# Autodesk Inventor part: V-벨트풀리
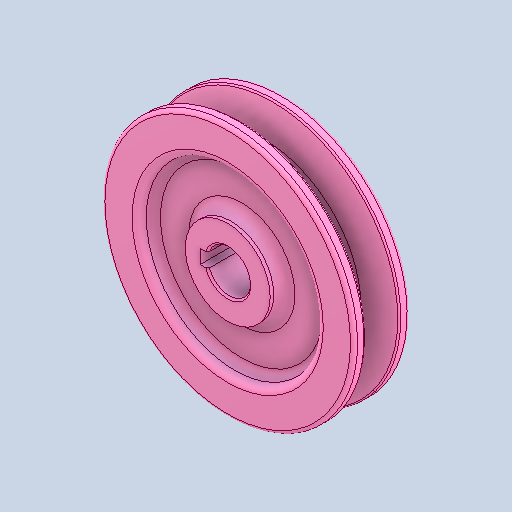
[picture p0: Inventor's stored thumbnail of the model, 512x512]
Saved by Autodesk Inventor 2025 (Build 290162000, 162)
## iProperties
Created: 2024-08
Part Number: V-벨트풀리
Material: 강철, 연강
Document SubType Name: Modeling
Designer: SAMSUNG
Density: 7.86 g/cm^3
Appearance: 기본값
Author: jhkim
Sending System: Autodesk Inventor 2025
Preprocessor: ST-DEVELOPER v20
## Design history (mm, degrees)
feature "Solid1"
node "솔리드1"
